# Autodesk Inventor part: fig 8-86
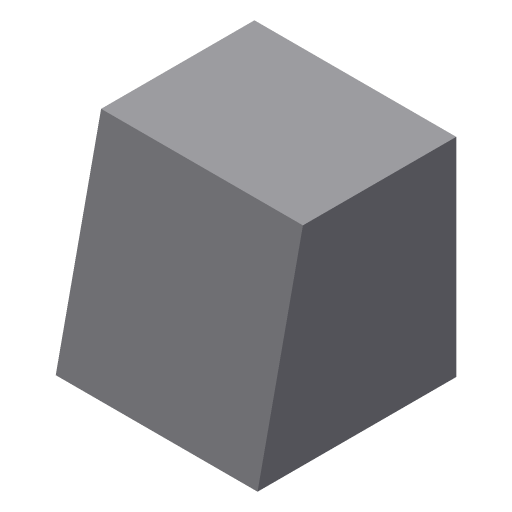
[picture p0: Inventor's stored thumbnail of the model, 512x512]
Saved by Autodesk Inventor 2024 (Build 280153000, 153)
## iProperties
Created: 2009-04
Part Number: fig 8-86
Document SubType Name: Modeling
Designer: Sham
Density: 1 g/cm^3
Material: Generic
Appearance: Default
Author: Sham
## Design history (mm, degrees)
sketch "Sketch5"
  geometry: L1 (14, -14.426)-(0, -14.426); L2 (0, -14.426)-(0, 0); L3 (0, 0)-(14, 0); L4 (14, 0)-(14, -14.426)
  constraints: 8 end point
extrude "Extrusion2" new body sketch "Sketch5" distance "d3" = 20; taper "d4" = 0 deg
sketch "Sketch7"
  geometry: L1 (-2.91, 10)-(18.11, 5.415)
  constraints: 2 end point
split "Split9" sketch "Sketch7"
body "Solid2"
